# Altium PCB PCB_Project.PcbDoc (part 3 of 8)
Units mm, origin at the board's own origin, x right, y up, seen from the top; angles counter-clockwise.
Board outline 250 x 200 mm, 6 copper layers (Top Shielding/Sig, Sig 1, PWR, GND, Sig 4, Bottom Shielding/Sig), stack 1.568 mm thick; 736 components, 420 nets, 1929 pads, 2185 vias.
Unrouted connection lines stored in the file: 47.
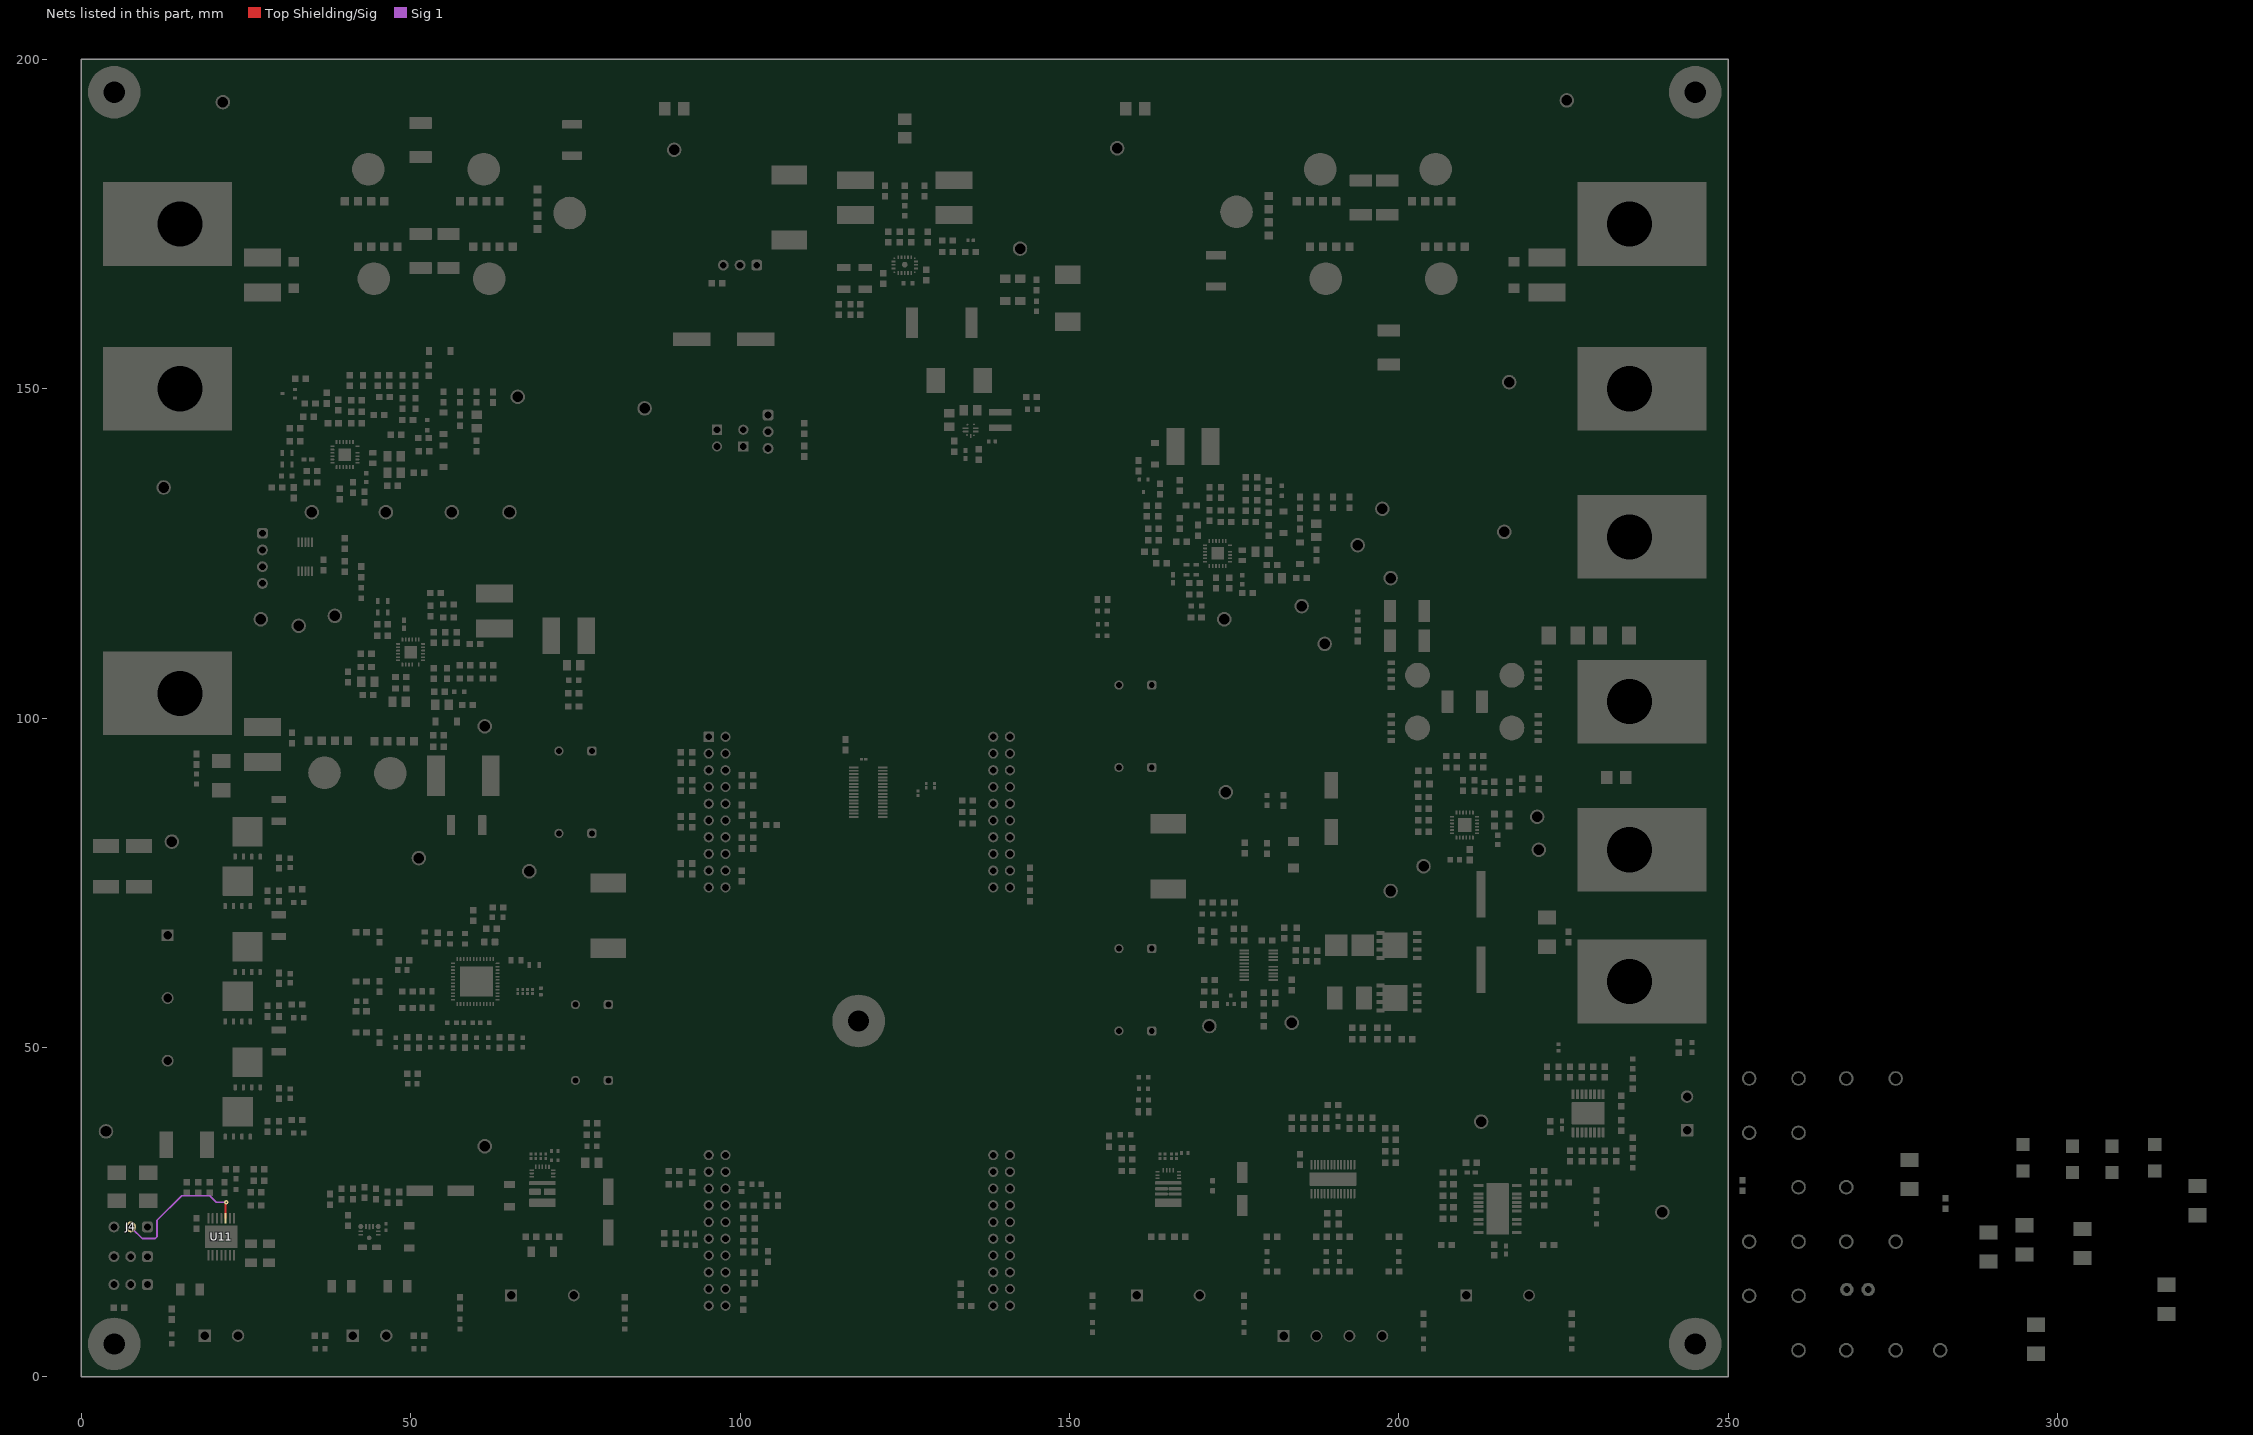
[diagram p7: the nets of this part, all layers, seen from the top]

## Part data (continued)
C44 C46 C64 C65 C118 C119 C124 C139 C146 C150 C154: library part CMP-0081011-1, "CAP, CERM, 0.1 µF, 100 V,+/- 10%, X7R, AEC-Q200 Grade 1, 0603", Cap_Case=0603, Manufacturer="Taiyo Yuden", Supplier Part Number 1=587-6009-1-ND, TempCo=X7R, Tolerance_%=10%, Value2=100V, ValueDisplayed=0.1µF
C45 C120 C123 C151 C153: library part CMP-0007082-4, "CAP, CERM, 0.01 uF, 100 V, +/- 10%, X7R, AEC-Q200 Grade 1, 0603", Cap_Case=0603, Manufacturer=TDK, Supplier Part Number 1=445-5812-1-ND, TempCo=X7R, Tolerance_%=10%, Value1="0.235428 ohm", Value2=100V, ValueDisplayed=0.01uF
C49: library part CMP-0007094-5, "CAP, CERM, 0.22 uF, 50 V, +/- 10%, X7R, AEC-Q200 Grade 1, 0603", Cap_Case=0603, Manufacturer=TDK, PartNumber=CGA3E3X7R1H224K080AB, Supplier Part Number 1=445-6926-1-ND, TempCo=X7R, Tolerance_%=10%, Value1="0.021699 ohm", Value2=50V, ValueDisplayed=0.22uF
C51 C125 C155: library part CMP-0007969-2, "CAP, CERM, 0.1 uF, 100 V, +/- 10%, X7R, AEC-Q200 Grade 1, 0805", Cap_Case=0805, Manufacturer=TDK, Supplier Part Number 1=445-5827-1-ND, TempCo=X7R, Tolerance_%=10%, Value1="0.020726 ohm", Value2=100V, ValueDisplayed=0.1uF
C52 C53 C58 C131 C133 C160 C162: library part CMP-0007079-4, "CAP, CERM, 0.047 uF, 50 V, +/- 10%, X7R, AEC-Q200 Grade 1, 0603", Cap_Case=0603, Manufacturer=TDK, Supplier Part Number 1=445-5664-1-ND, TempCo=X7R, Tolerance_%=10%, Value1="0.049007 ohm", Value2=50V, ValueDisplayed=0.047uF
C54 C127 C157: library part CMP-0006687-2, "CAP, CERM, 330 pF, 50 V, +/- 10%, X7R, 0402", Cap_Case=0402, Manufacturer=MuRata, Supplier Part Number 1=490-3247-1-ND, TempCo=X7R, Tolerance_%=10%, Value1=Unknown, Value2=50V, ValueDisplayed=330pF
C55: library part CMP-0007080-5, "CAP, CERM, 0.068 uF, 50 V, +/- 10%, X7R, AEC-Q200 Grade 1, 0603", Cap_Case=0603, Manufacturer=TDK, Supplier Part Number 1=445-5665-1-ND, TempCo=X7R, Tolerance_%=10%, Value1="0.035979 ohm", Value2=50V, ValueDisplayed=0.068uF
C56 C57 C130 C132 C159 C161: library part CMP-0006921-4, "CAP, CERM, 330 pF, 50 V, +/- 10%, X7R, 0603", Cap_Case=0603, Manufacturer=Kemet, Supplier Part Number 1=399-1073-1-ND, TempCo=X7R, Tolerance_%=10%, Value1=Unknown, Value2=50V, ValueDisplayed=330pF
C59 C129 C158: library part CMP-0095670-2, "Cap Ceramic 0.1uF 25V X7R 10% Pad SMD 0603 Soft Termination +125°C Automotive T/R", Manufacturer=Murata, Operating Temperature Range="-55°C to +125°C", TempCo=15%, Temperature Characteristic=X7R, Tolerance_%=10%, ValueDisplayed=0.1uF
C60 C61: library part CMP-0093675-1, "4.7uF ±10% 100V Ceramic Capacitor X7S 1210 (3225 Metric)", Manufacturer=Murata, Operating Temperature Range="-55°C to +125°C", TempCo=22%, Temperature Characteristic=X7S, Tolerance_%=10%, ValueDisplayed=4.7uF
C62 C63: library part CMP-0123888-1, "Ceramic Capacitor, 1206, 22uF, 20%, X7R, 15%, 16V", Manufacturer="Taiyo Yuden", Operating Temperature Range="-55°C to +125°C", TempCo=15%, Temperature Characteristic=X7R, Tolerance_%=20%, ValueDisplayed=22uF, Voltage=16V
C66: library part CMP-0081259-1, "CAP, CERM, 1 µF, 35 V,+/- 10%, X7R, AEC-Q200 Grade 1, 0603", Cap_Case=0603, Manufacturer=TDK, Supplier Part Number 1=445-174339-1-ND, TempCo=X7R, Tolerance_%=10%, Value2=35V, ValueDisplayed=1µF
C67: library part CMP-0011225-2, "CAP, AL, 47 uF, 100 V, +/- 20%, 0.32 ohm, AEC-Q200 Grade 2, SMD", Cap_Case=H13, Manufacturer=Panasonic, Supplier Part Number 1=PCE3497CT-ND, Tolerance_%=20%, Value1="0.32 ohm", Value2=100V, ValueDisplayed=47uF
C68: library part CMP-0122034-1, "10 pF ±10% 50V Ceramic Capacitor X7R 0402 (1005 Metric)", Digikey Part Number=399-C0402C100K5RAC7867CT-ND, Manufacturer=KEMET, Operating Temperature Range="-55°C to +125°C", TempCo=15%, Temperature Characteristic=X7R, Tolerance_%=10%, ValueDisplayed=10pF
C69: library part CMP-0008305-2, "CAP, CERM, 22 uF, 25 V, +/- 20%, X5R, 0805", Cap_Case=0805, Manufacturer=MuRata, Supplier Part Number 1=490-10749-1-ND, TempCo=X5R, Tolerance_%=20%, Value1=Unknown, Value2=25V, ValueDisplayed=22uF
C70: library part CMP-0008378-2, "CAP, CERM, 10 uF, 25 V, +/- 10%, X7R, 0805", Cap_Case=0805, Manufacturer=MuRata, Supplier Part Number 1=81-GRM21BZ71E106KE5L, TempCo=X7R, Tolerance_%=10%, Value1=Unknown, Value2=25V, ValueDisplayed=10uF
C71: library part CMP-0006696-2, "CAP, CERM, 6800 pF, 50 V, +/- 10%, X7R, 0402", Cap_Case=0402, Manufacturer=MuRata, Supplier Part Number 1=490-4515-1-ND, TempCo=X7R, Tolerance_%=10%, Value1=Unknown, Value2=50V, ValueDisplayed=6800pF
C72 C78 C81 C84 C86 C89 C90 C91: library part CMP-0007086-4, "CAP, CERM, 0.022 uF, 100 V, +/- 10%, X7R, AEC-Q200 Grade 1, 0603", Cap_Case=0603, Manufacturer=TDK, Supplier Part Number 1=445-5814-1-ND, TempCo=X7R, Tolerance_%=10%, Value1="0.083542 ohm", Value2=100V, ValueDisplayed=0.022uF
C73 C75 C82: library part CMP-0006356-2, "CAP, CERM, 0.1 uF, 50 V, +/- 10%, X7R, AEC-Q200 Grade 1, 0402", Cap_Case=0402, Manufacturer=MuRata, Supplier Part Number 1=490-10672-1-ND, TempCo=X7R, Tolerance_%=10%, Value1=Unknown, Value2=50V, ValueDisplayed=0.1uF
C77 C80: library part CMP-0007050-1, "CAP, CERM, 0.47 uF, 50 V, +/- 10%, X7R, 0603", Cap_Case=0603, Manufacturer=TDK, Supplier Part Number 1=445-5952-1-ND, TempCo=X7R, Tolerance_%=10%, Value1="0.010974 ohm", Value2=50V, ValueDisplayed=0.47uF
C87: library part CMP-0079579-1, "CAP, CERM, 0.22 µF, 50 V,+/- 10%, X7R, AEC-Q200 Grade 1, 0603", Cap_Case=0603, Manufacturer=MuRata, Supplier Part Number 1=490-14410-1-ND, TempCo=X7R, Tolerance_%=10%, Value2=50V, ValueDisplayed=0.22µF
C88 C92 C102 C140 C141 C142: library part CMP-0079095-1, "CAP, CERM, 0.1 µF, 50 V,+/- 10%, X7R, AEC-Q200 Grade 1, 0603", Cap_Case=0603, Manufacturer=AVX, Supplier Part Number 1=478-3540-1-ND, TempCo=X7R, Tolerance_%=10%, Value2=50V, ValueDisplayed=0.1µF
C93: library part CMP-0006850-4, "CAP, CERM, 0.01 uF, 50 V, +/- 5%, X7R, 0603", Cap_Case=0603, Manufacturer=Kemet, Supplier Part Number 1=399-1092-1-ND, TempCo=X7R, Tolerance_%=5%, Value1=Unknown, Value2=50V, ValueDisplayed=0.01uF
C94 C99 C100: library part CMP-0084736-1, "CAP, CERM, 0.1 µF, 50 V,+/- 10%, X7R, AEC-Q200 Grade 0, 0603", Cap_Case=0603, Manufacturer=AVX, TempCo=X7R, Tolerance_%=10%, Value2=50V, ValueDisplayed=0.1µF
C95: library part CMP-0077295-1, "CAP, AL, 100 µF, 50 V, +/- 20%, 0.18 ohm, AEC-Q200 Grade 2, SMD", Cap_Case=8x10.2mm, Manufacturer=Panasonic, Supplier Part Number 1=P19726CT-ND, Tolerance_%=20%, Value1="0.18 ohm", Value2=50V, ValueDisplayed=100µF
C96: library part CMP-0007353-5, "CAP, CERM, 2.2 uF, 50 V, +/- 10%, X5R, 0603", Cap_Case=0603, Manufacturer=MuRata, Supplier Part Number 1=490-10733-1-ND, TempCo=X5R, Tolerance_%=10%, Value1=Unknown, Value2=50V, ValueDisplayed=2.2uF
C97: library part CMP-0093561-1, "Cap Ceramic 5.6nF 50V X7R ±10% Pad SMD 0603 +125°C T/R", Manufacturer=Samsung, Operating Temperature Range="-55°C to +125°C", TempCo=0.15, Temperature Characteristic=X7R, Tolerance_%=10%, ValueDisplayed=5.6nF
C98: library part CMP-0007094-5, "CAP, CERM, 0.22 uF, 50 V, +/- 10%, X7R, AEC-Q200 Grade 1, 0603", Cap_Case=0603, Manufacturer=TDK, Supplier Part Number 1=445-6926-1-ND, TempCo=X7R, Tolerance_%=10%, Value1="0.021699 ohm", Value2=50V, ValueDisplayed=0.22uF
C101: library part CMP-0006922-4, "CAP, CERM, 3300 pF, 50 V, +/- 10%, X7R, 0603", Cap_Case=0603, Manufacturer=Kemet, Supplier Part Number 1=399-1086-1-ND, TempCo=X7R, Tolerance_%=10%, Value1=Unknown, Value2=50V, ValueDisplayed=3300pF
C103 C104 C111: library part CMP-0008495-2, "CAP, CERM, 0.022 uF, 100 V, +/- 5%, X7R, 1206", Cap_Case=1206, Manufacturer=AVX, Supplier Part Number 1=478-3789-1-ND, TempCo=X7R, Tolerance_%=5%, Value1="0.079 ohm", Value2=100V, ValueDisplayed=0.022uF
C107: library part CMP-0008709-1, "CAP, CERM, 0.1 uF, 100 V, +/- 10%, X7R, 1206", Cap_Case=1206_180, Manufacturer=TDK, Supplier Part Number 1=445-1377-1-ND, TempCo=X7R, Tolerance_%=10%, Value1="0.030343 ohm", Value2=100V, ValueDisplayed=0.1uF
C108 C166 C170 C176 C178 C183 C185: library part CMP-0079247-1, "CAP, CERM, 4700 pF, 100 V,+/- 10%, X7R, AEC-Q200 Grade 1, 0603", Cap_Case=0603, Manufacturer=MuRata, Supplier Part Number 1=490-4930-1-ND, TempCo=X7R, Tolerance_%=10%, Value2=100V, ValueDisplayed=4700pF
C109: library part CMP-0008881-2, "CAP, CERM, 0.1 uF, 100 V, +/- 10%, X7R, 1206", Cap_Case=1206, Manufacturer=MuRata, Supplier Part Number 1=490-3364-1-ND, TempCo=X7R, Tolerance_%=10%, Value1=Unknown, Value2=100V, ValueDisplayed=0.1uF
C110: library part CMP-0008713-2, "CAP, CERM, 0.22 uF, 100 V, +/- 10%, X7R, 1206", Cap_Case=1206, Manufacturer=TDK, Supplier Part Number 1=445-2283-1-ND, TempCo=X7R, Tolerance_%=10%, Value1="0.01493 ohm", Value2=100V, ValueDisplayed=0.22uF
C112 C128 C199: library part CMP-0007135-2, "CAP, CERM, 0.1 uF, 16 V, +/- 10%, X7R, AEC-Q200 Grade 1, 0603", Cap_Case=0603, Manufacturer=MuRata, Supplier Part Number 1=490-8015-1-ND, TempCo=X7R, Tolerance_%=10%, Value1=Unknown, Value2=16V, ValueDisplayed=0.1uF
C114 C116 C122 C144 C147 C152: library part CMP-0077895-3, "CAP, CERM, 0.22 µF, 100 V,+/- 20%, X7S, AEC-Q200 Grade 1, 0603", Cap_Case=0603, Manufacturer="Taiyo Yuden", Supplier Part Number 1=587-5013-1-ND, TempCo=X7S, Tolerance_%=20%, Value2=100V, ValueDisplayed=0.22µF
C134: library part CMP-0007430-2, "CAP, CERM, 0.082 uF, 25 V, +/- 10%, X7R, 0603", Cap_Case=0603, Manufacturer=MuRata, Supplier Part Number 1=GRM188R71E823KA01D-ND, TempCo=X7R, Tolerance_%=10%, Value1=Unknown, Value2=25V, ValueDisplayed=0.082uF
C135: library part CMP-0011162-2, "CAP, AL, 220 uF, 63 V, +/- 20%, 0.16 ohm, SMD", Cap_Case=12.5x13.5, Manufacturer="Cornell Dubilier Electronics", Supplier Part Number 1=338-2175-1-ND, Tolerance_%=20%, Value1="0.16 ohm", Value2=63V, ValueDisplayed=220uF
C136: library part CMP-0007078-1, "CAP, CERM, 0.1 uF, 50 V, +/- 10%, X7R, AEC-Q200 Grade 1, 0603", Cap_Case=0603, Manufacturer=TDK, Supplier Part Number 1=445-5666-1-ND, TempCo=X7R, Tolerance_%=10%, Value1="0.0296 ohm", Value2=50V, ValueDisplayed=0.1uF
C137 C138: library part CMP-0006901-3, "CAP, CERM, 0.022 uF, 50 V, +/- 10%, X7R, 0603", Cap_Case=0603, Manufacturer=Kemet, Supplier Part Number 1=399-1280-1-ND, TempCo=X7R, Tolerance_%=10%, Value1=Unknown, Value2=50V, ValueDisplayed=0.022uF
C163: library part CMP-0123897-1, "Auto Grade Capacitor, 0603, X7R, 25V, 1uF, ±10%", Digikey Part Number=2679-AGC0603X7R250-105KXPTR-ND, Manufacturer=Venkel, Operating Temperature Range="-55°C to +125°C", TempCo=15%, Temperature Characteristic=X7R, Tolerance_%=10%, ValueDisplayed=1uF
C164: library part CMP-0007007-3, "CAP, CERM, 10 uF, 25 V, +/- 20%, X5R, 0603", Cap_Case=0603, Manufacturer=TDK, Supplier Part Number 1=445-9015-1-ND, TempCo=X5R, Tolerance_%=20%, Value1="0.004639 ohm", Value2=25V, ValueDisplayed=10uF
C165 C169 C175 C177 C182 C184: library part CMP-0007148-4, "CAP, CERM, 3300 pF, 100 V, +/- 10%, X7R, AEC-Q200 Grade 1, 0603", Cap_Case=0603, Manufacturer=MuRata, Supplier Part Number 1=GCM188R72A332KA37D-ND, TempCo=X7R, Tolerance_%=10%, Value1=Unknown, Value2=100V, ValueDisplayed=3300pF
C167: library part CMP-0007007-3, "CAP, CERM, 10 uF, 25 V, +/- 20%, X5R, 0603", Cap_Case=0603, Manufacturer=TDK, PartNumber=C1608X5R1E106M080AC, Supplier Part Number 1=445-9015-1-ND, TempCo=X5R, Tolerance_%=20%, Value1="0.004639 ohm", Value2=25V, ValueDisplayed=10uF
C168 C174 C180: library part CMP-0085951-1, "CAP, CERM, 10 µF, 75 V,+/- 20%, X7R, AEC-Q200 Grade 1, 1210", Cap_Case=1210, Manufacturer=TDK, TempCo=X7R, Tolerance_%=20%, Value2=75V, ValueDisplayed=10µF
C171 C172: library part CMP-0125363-1, "1 µF ±10% 100V Ceramic Capacitor X7T 0603 (1608 Metric)", Digikey Part Number=490-GRM188D72A105KE01DCT-ND, Manufacturer=Murata, Mouser Part Number=81-GRM188D72A105KE1D, Operating Temperature Range="-55°C to +125°C", TempCo=+22/-33%, Temperature Characteristic=X7T, Tolerance_%=10%, ValueDisplayed=1uF
C173 C179 C181: library part CMP-0121052-1, "Cap Ceramic 1uF 25V X7R ±10% Pad SMD 0603 +125°C T/R", Digikey Part Number=1276-CL10B105KA8VPJCCT-ND, Manufacturer=Samsung, Mouser Part Number=187-CL10B105KA8VPJC, Operating Temperature Range="-55°C to +125°C", TempCo=15%, Temperature Characteristic=X7R, Tolerance_%=10%, ValueDisplayed=1uF
C186 C187 C188: library part CMP-0006940-4, "CAP, CERM, 470 pF, 50 V, +/- 10%, X7R, 0603", Cap_Case=0603, Manufacturer=Kemet, Supplier Part Number 1=399-1075-1-ND, TempCo=X7R, Tolerance_%=10%, Value1=Unknown, Value2=50V, ValueDisplayed=470pF
C189: library part CMP-0121051-1, "Automotive CAP, 100㎋, 25V, ±10%, X7R, 0603, 5mm Bending", Manufacturer=Samsung, Mouser Part Number=187-CL10B104KA8VPJC, Operating Temperature Range="-55°C to +125°C", TempCo=15%, Temperature Characteristic=X7R, Tolerance_%=10%, ValueDisplayed=100nF
D1 D2 D4 D5 D7 D11 D13 D15 D16 D17 D18 D20 D21 D22 D23 D27 D29 D30 D31 D35 D40 D47 D48 D49: library part CMP-0078478-1, "LED, Green, SMD", Color=Green, Manufacturer=Lite-On, Power_TotalModule=75mW, Supplier Part Number 1=160-1446-1-ND, Value1=0.075W, Value2=2V
D3 D9 D14 D19 D28 D37 D41 D42 D46 D50: library part CMP-0002893-1, "LED, Super Red, SMD", Color="super red", Manufacturer="Wurth Elektronik", Supplier Part Number 1=732-4979-1-ND, Value1=W, Value2=1.9V
D6 D38 D59 D60 D61 D62 D63 D64 D65: library part CMP-0028987-2, "Diode, Schottky, 100 V, 2 A, SMB", Manufacturer=Vishay-Semiconductor, Value1=2A, Value2=0.79V
D8 D36 D45 D51 D52 D53 D54: library part CMP-0076974-1, "Diode, Switching, 100 V, 0.15 A, SOD-123", Manufacturer="Micro Commercial Components", Supplier Part Number 1=1N4148WTPMSCT-ND, Value1=0.15A, Value2=1.25V
D10: library part CMP-0077028-2, "Diode, Ultrafast, 400 V, 3 A, SMC", Manufacturer=Vishay-Semiconductor, Value1=3A, Value2=1.1V
D12: library part CMP-0067546-2, "Diode, Superfast Rectifier, 600 V, 5 A, SMC", Manufacturer="SMC Diode Solutions", Value1=5A, Value2=1.7V
D24 D32 D33 D43: library part CMP-0029014-2, "Diode, Ultrafast, 400 V, 1 A, 1408 Diode", Manufacturer=Bourns, Value1=1A, Value2=1.05V
D25 D26: library part CMP-0005541-4, "Diode, TVS, Uni, 13 V, 21.5 Vc, SMB", Manufacturer="Diodes Inc.", Value1=600W
D34 D44: library part CMP-0085022-1, "Diode, TVS, Bi, 51 V, 82.4 Vc, 400 W, 4.9 A, SMA (non-polarized)", Manufacturer=Littelfuse, Value1=82.4V
D39: library part CMP-0085010-1, "Diode, TVS, Bi, 20 V, 32.4 Vc, 400 W, 12.3 A, SMA (non-polarized)", Manufacturer=Littelfuse, Value1=32.4V
D55 D56 D57 D58: library part CMP-0028752-1, "Diode, Schottky, 150 V, 1 A, SMA", Manufacturer=STMicroelectronics, Supplier Part Number 1=497-7545-1-ND, Value1=1A, Value2=0.78V
H1 H2 H3 H4 H5: library part CMP-0003617-1, "Machine Screw, Round, #4-40 x 1/4, Nylon, Philips panhead", Manufacturer="B&F Fastener Supply", Supplier Part Number 1=H542-ND
H6 H7 H8 H9 H10: library part CMP-0003610-1, "Standoff, Hex, 0.5\"L #4-40 Nylon", Manufacturer=Keystone, Supplier Part Number 1=36-1902C-ND
J1 J2 J3 J4 J19: library part CMP-0075407-2, "Header, 100mil, 3x1, Gold, TH", Color=Black, Current_A=6.3A, Manufacturer=Samtec, PartNumber=TSW-103-07-G-S, Supplier Part Number 1=SAM1029-03-ND, Voltage_V=550V
J5: library part CMP-0055528-1, "Terminal Block, 9.52mm, 3x1, R/A, TH", Color=Green, Current_A=32A, Manufacturer="Phoenix Contact", PartNumber=1904150, Supplier Part Number 1=277-6184-ND, Voltage_V=1kV
J6 J7 J11: library part CMP-0055471-1, "Terminal Block, 5.08 mm, 2x1, TH", Color=Green, Current_A=17.5A, Manufacturer="Phoenix Contact", PartNumber=1715721, Supplier Part Number 1=277-1263-ND, Voltage_V=400V
J8 J9 J10: library part CMP-0055527-1, "Terminal Block, 9.52mm, 2x1, R/A, TH", Color=Green, Current_A=32A, Manufacturer="Phoenix Contact", PartNumber=1902547, Supplier Part Number 1=277-5951-ND, Voltage_V=1kV
J12: library part CMP-0055526-1, "Terminal Block, 5mm, 4x1, R/A,TH", Color=Green, Current_A=17.5A, Manufacturer="Phoenix Contact", PartNumber=1715048, Supplier Part Number 1=277-1260-ND, Voltage_V=400V
J13: library part CMP-0003837-2, "Receptacle, 2.54mm, 10x2, Tin, TH", Alternate Manufacturer="Major League Electronics", Alternate PartNumber=CRD-081413-A-G, Manufacturer=Samtec, Supplier Part Number 1=SAM1204-10-ND
J14: library part CMP-0078266-2, "Receptacle, 2.54mm, 10x2, Tin, TH", Alternate Manufacturer="Major League Electronics", Alternate PartNumber=CRD-081413-A-G, Manufacturer=Samtec, Supplier Part Number 1=SAM1204-10-ND
J15: library part CMP-0081071-3, "Receptacle, 2.54mm, 10x2, Tin, TH", Alternate Manufacturer="Major League Electronics", Alternate PartNumber=CRD-081413-A-G, Manufacturer=Samtec, Supplier Part Number 1=SAM1204-10-ND
J16 J17: library part CMP-0075286-1, "Header, 2.54mm, 2x1, Gold, TH", Color=Black, Current_A=3A, Manufacturer=Foxconn, PartNumber=HB3902U, Voltage_V=500V
J18: library part CMP-0081070-3, "Receptacle, 2.54mm, 10x2, Tin, TH", Alternate Manufacturer="Major League Electronics", Alternate PartNumber=CRD-081413-A-G, Manufacturer=Samtec, Supplier Part Number 1=SAM1204-10-ND
J20: library part CMP-0075409-2, "Header, 100mil, 4x1, Gold, TH", Color=Black, Current_A=6.3A, Manufacturer=Samtec, PartNumber=TSW-104-07-G-S, Supplier Part Number 1=SAM1029-04-ND, Voltage_V=550V
L1 L2: library part CMP-0063986-1, "Inductor, Shielded Drum Core, Ferrite, 1 uH, 24 A, 0.0012 ohm, SMD", Manufacturer="Wurth Elektronik", Supplier Part Number 1=732-2138-1-ND, Value1="0.0012 ohm", Value2=24A, ValueDisplayed=1uH
L3: library part CMP-0063847-1, "Inductor, Shielded Drum Core, Ferrite, 2.2 uH, 5.9 A, 0.0104 ohm, SMD", Manufacturer="Wurth Elektronik", Supplier Part Number 1=732-1055-1-ND, Value1="0.0104 ohm", Value2=5.9A, ValueDisplayed=2.2uH
L4: library part CMP-0064538-2, "Inductor, Shielded Drum Core, Ferrite, 22 uH, 5.3 A, 0.0233 ohm, SMD", Manufacturer="Wurth Elektronik", Supplier Part Number 1=732-1243-1-ND, Value1="0.0233 ohm", Value2=5.3A, ValueDisplayed=22uH
L5: library part CMP-0090842-1, "Power Inductor, shielded, composite, 1uH 20% tol, DCR 7.2mOhms, SRF 65MHz, Isat 4.8A, Irms 13A, AEC-Q200", Manufacturer=Coilcraft, Operating Temperature Range="to +165°C", Self Resonant Frequency=65MHz, Test Frequency=1MHz, Tolerance_%=20%
LBL1: library part CMP-0003625-1, "Thermal Transfer Printable Labels, 0.650\" W x 0.200\" H - 10,000 per roll", Manufacturer=Brady, Supplier Part Number 1=97C5133
LOGO1: library part CMP-0074837-1, "IEC 61010-1 Hot Surface Warning"
Logo2: library part CMP-0074844-1
Logo3: library part CMP-0074838-1, "Texas Instrument Corporate Signature"
Logo4: library part CMP-0074847-1, "FCC_disclaimer"
Logo5: library part CMP-0074769-1
Q1 Q2 Q7 Q9 Q10 Q11 Q12 Q17 Q18 Q19 Q20 Q21: library part CMP-0088066-1, "N-Channel Power MOSFET 80V 3374A 1.1mOhm 8-Pin DFNW Surface Mount T/R", Manufacturer="ON Semiconductor"
Q3 Q4 Q5 Q6: library part CMP-0098150-1, "Trans MOSFET N-CH 40V 190A Automotive 5-Pin(4+Tab) LFPAK T/R", Digikey Part Number=1727-7419-1-ND, Drain To Source Breakdown Voltage=42V, Input Capacitace At Vds="5436pF @ 25V", Manufacturer=Nexperia, Mouser Part Number=771-BUK7J1R4-40HX, Operating Temperature Range="-55°C to +175°C", Power_W=395W, Pulse Drain Current=600A, Typ Forward Diode Voltage=0.8V
Q13 Q22: library part CMP-0000757-1, "MOSFET, N-CH, 50 V, 0.2 A, SOT-323", Alternate Manufacturer=None, Manufacturer="Diodes Inc.", Supplier Part Number 1=BSS138W-FDICT-ND, Value1=3
Q14 Q15: library part CMP-0000870-1, "MOSFET, N-CH, 60 V, 60 A, PowerPAK SO-8", Alternate Manufacturer=None, Manufacturer=Vishay-Semiconductor, Supplier Part Number 1=SIR662DP-T1-GE3CT-ND, Value1=0.002, Value2="96 nC"
Q16: library part CMP-0000428-2, "Transistor, NPN, 40 V, 0.2 A, SOT-416", Manufacturer="ON Semiconductor", Supplier Part Number 1=MMBT3904TT1GOSCT-ND, Value1="0.2 A", Value2=300
Q23 Q24 Q25 Q26 Q27 Q28: library part CMP-0000962-2, "MOSFET, N-CH, 100 V, 10 A, DQJ0008A (VSONP-8)", Alternate Manufacturer=None, Manufacturer="Texas Instruments", Value2="17 nC"
R1 R2 R69 R70 R77 R78 R105 R106 R107 R108 R116 R199: library part CMP-0023266-5, "RES, 750, 1%, 0.1 W, 0603", Manufacturer=Yageo, Power_W=100mW, Supplier Part Number 1=311-750HRCT-ND, TempCo="100 ppm/C", Tolerance_%=1%, Value2=0.1W, Value_Code=750R, ValueDisplayed=750
R3 R39 R64 R104 R136 R183 R214 R215 R244 R267: library part CMP-0022904-5, "RES, 205, 1%, 0.1 W, 0603", Manufacturer=Yageo, Power_W=100mW, Supplier Part Number 1=311-205HRCT-ND, TempCo="100 ppm/C", Tolerance_%=1%, Value2=0.1W, Value_Code=205R, ValueDisplayed=205
R4: library part CMP-0025886-3, "RES, 10 k, 5%, 0.1 W, 0603", Manufacturer="Yageo America", Power_W=100mW, Supplier Part Number 1=311-10KGRCT-ND, TempCo="100 ppm/C", Tolerance_%=5%, Value2=0.1W, Value_Code=10k0, ValueDisplayed=10k
R5 R12: library part CMP-0025697-4, "RES, 0, 5%, 0.1 W, AEC-Q200 Grade 0, 0603", Manufacturer=Vishay-Dale, PartNumber=CRCW06030000Z0EA, Power_W=100mW, Supplier Part Number 1=541-0.0GCT-ND, TempCo="200 ppm/C", Tolerance_%=5%, Value2=0.1W, Value_Code=0000, ValueDisplayed=0
R6 R18 R61 R88 R257: library part CMP-0094798-1, "Res Thick Film 0402 10K Ohm 5% 0.063W(1/16W) ±100ppm/C Pad SMD T/R", Digikey Part Number=311-10KJRCT-ND, Manufacturer=YAGEO, Mouser Part Number=603-RC0402JR-0710KL, Operating Temperature Range="-55°C to +155°C", Power_W=63mW, TempCo=100ppm/°C, Tolerance_%=5%
R7 R9 R10 R11 R13 R17 R19 R20 R256 R258 R259 R260 R293 R294 R295 R296: library part CMP-0027500-1, "RES, 22.0, 1%, 0.05 W, 0201", Manufacturer="Yageo America", Power_W=50mW, Supplier Part Number 1=YAG2518CT-ND, TempCo="200 ppm/C", Tolerance_%=1%, Value2=0.05W, Value_Code=22R0, ValueDisplayed=22.0
R8: library part CMP-0022109-5, "RES, 1.00 k, 1%, 0.1 W, AEC-Q200 Grade 0, 0603", Manufacturer=Vishay-Dale, Power_W=100mW, Supplier Part Number 1=541-1.00KHCT-ND, TempCo="100 ppm/C", Tolerance_%=1%, Value2=0.1W, Value_Code=1k00, ValueDisplayed=1.00k
R14 R176 R178 R181 R185 R187 R237 R239 R242 R246 R248 R302: library part CMP-0022895-5, "RES, 1.00 k, 1%, 0.1 W, 0603", Manufacturer=Yageo, Power_W=100mW, Supplier Part Number 1=311-1.00KHRCT-ND, TempCo="100 ppm/C", Tolerance_%=1%, Value2=0.1W, Value_Code=1k00, ValueDisplayed=1.00k
R15 R16 R30 R139 R140 R150 R161 R253 R254 R255: library part CMP-0022990-5, "RES, 2.49 k, 1%, 0.1 W, 0603", Manufacturer=Yageo, Power_W=100mW, Supplier Part Number 1=311-2.49KHRCT-ND, TempCo="100 ppm/C", Tolerance_%=1%, Value2=0.1W, Value_Code=2k49, ValueDisplayed=2.49k
R21 R153 R216: library part CMP-0098465-1, "1 Ohms ±1% 3W Chip Resistor 2010 (5025 Metric) Automotive AEC-Q200, Current Sense, Moisture Resistant, Pulse Withstanding", Digikey Part Number=4423-VMP-1R00-1.0-UCT-ND, Manufacturer=Isabellenhuette, Operating Temperature Range="-65°C to +170°C", Power_W=3W, TempCo=20ppm/°C, Tolerance_%=1%
R22 R23 R24 R28 R29 R32 R38 R117 R154 R155 R157 R163 R164 R165 R179 R182 R196 R197 R204 R206 R209 R217 R218 R219 R224 R225 R226 R240 R243 R305: library part CMP-0025697-4, "RES, 0, 5%, 0.1 W, AEC-Q200 Grade 0, 0603", Manufacturer=Vishay-Dale, Power_W=100mW, Supplier Part Number 1=541-0.0GCT-ND, TempCo="200 ppm/C", Tolerance_%=5%, Value2=0.1W, Value_Code=0000, ValueDisplayed=0
R25 R158 R174 R221 R234: library part CMP-0021863-2, "RES, 10.0, 1%, 0.125 W, 0805", Manufacturer="Yageo America", Power_W=125mW, Supplier Part Number 1=311-10.0CRCT-ND, TempCo="200 ppm/C", Tolerance_%=1%, Value2=0.125W, Value_Code=10R0, ValueDisplayed=10.0
R26: library part CMP-0092921-1, "Res Metal Strip 3921 0.0005 Ohm 1% 3W ±175ppm/°C Molded SMD SMD Embossed Plastic T/R", Digikey Part Number=WSLM-.0005CT-ND, Manufacturer="Vishay Dale", Mouser Part Number=71-WSL3921L5000FEA, Operating Temperature Range="-65°C to +170°C", Power_W=3W, TempCo=150ppm/°C, Tolerance_%=1%
R27 R166 R227: library part CMP-0022679-3, "RES, 100, 1%, 0.1 W, AEC-Q200 Grade 0, 0603", Manufacturer=Panasonic, Power_W=100mW, Supplier Part Number 1=P100HCT-ND, TempCo="100 ppm/C", Tolerance_%=1%, Value2=0.1W, Value_Code=100R, ValueDisplayed=100
R31 R58 R167 R168 R228 R229: library part CMP-0022902-5, "RES, 200, 1%, 0.1 W, 0603", Manufacturer=Yageo, Power_W=100mW, Supplier Part Number 1=311-200HRCT-ND, TempCo="100 ppm/C", Tolerance_%=1%, Value2=0.1W, Value_Code=200R, ValueDisplayed=200
R33 R169 R170 R171 R173 R193 R202 R230 R231 R232 R233: library part CMP-0023007-4, "RES, 2.21, 1%, 0.1 W, 0603", Manufacturer=Yageo, Power_W=100mW, Supplier Part Number 1=311-2.21HRCT-ND, TempCo="200 ppm/C", Tolerance_%=1%, Value2=0.1W, Value_Code=2R21, ValueDisplayed=2.21
R34: library part CMP-0021863-2, "RES, 10.0, 1%, 0.125 W, 0805", Manufacturer="Yageo America", PartNumber=RC0805FR-0710RL, Power_W=125mW, Supplier Part Number 1=311-10.0CRCT-ND, TempCo="200 ppm/C", Tolerance_%=1%, Value2=0.125W, Value_Code=10R0, ValueDisplayed=10.0
R35 R129 R130 R134 R138 R141 R142 R149 R152 R304: library part CMP-0023626-3, "RES, 10.0 k, 0.01%, 0.063 W, 0603", Manufacturer="Stackpole Electronics Inc", Power_W=63mW, Supplier Part Number 1=RNCF0603TKY10K0CT-ND, TempCo="5 ppm/C", Tolerance_%=0.01%, Value2=0.063W, Value_Code=10k0, ValueDisplayed=10.0k
R36: library part CMP-0023288-5, "RES, 820, 1%, 0.1 W, 0603", Manufacturer=Yageo, Power_W=100mW, Supplier Part Number 1=311-820HRCT-ND, TempCo="100 ppm/C", Tolerance_%=1%, Value2=0.1W, Value_Code=820R, ValueDisplayed=820
R37 R180 R241: library part CMP-0023017-5, "RES, 309, 1%, 0.1 W, 0603", Manufacturer=Yageo, Power_W=100mW, Supplier Part Number 1=311-309HRCT-ND, TempCo="100 ppm/C", Tolerance_%=1%, Value2=0.1W, Value_Code=309R, ValueDisplayed=309
R40 R41 R184 R186 R245 R247 R262: library part CMP-0025686-1, "RES, 10.0 k, 0.1%, 0.1 W, AEC-Q200 Grade 1, 0603", Manufacturer=Vishay-Dale, Power_W=100mW, Supplier Part Number 1=TNP10.0KAACT-ND, TempCo="25 ppm/C", Tolerance_%=0.1%, Value2=0.1W, Value_Code=10k0, ValueDisplayed=10.0k
R42: library part CMP-0022449-4, "RES, 4.02 k, 1%, 0.1 W, AEC-Q200 Grade 0, 0603", Manufacturer=Vishay-Dale, Power_W=100mW, Supplier Part Number 1=541-4.02KHCT-ND, TempCo="100 ppm/C", Tolerance_%=1%, Value2=0.1W, Value_Code=4k02, ValueDisplayed=4.02k
R43: library part CMP-0022779-5, "RES, 12.0 k, 1%, 0.1 W, 0603", Manufacturer=Yageo, Power_W=100mW, Supplier Part Number 1=311-12.0KHRCT-ND, TempCo="100 ppm/C", Tolerance_%=1%, Value2=0.1W, Value_Code=12k0, ValueDisplayed=12.0k
R44 R190 R251 R261 R265 R266 R270 R273 R277: library part CMP-0021990-4, "RES, 100 k, 1%, 0.1 W, AEC-Q200 Grade 0, 0603", Manufacturer=Vishay-Dale, Power_W=100mW, Supplier Part Number 1=541-100KHCT-ND, TempCo="100 ppm/C", Tolerance_%=1%, Value2=0.1W, Value_Code=100k
R45 R127 R252: library part CMP-0023098-5, "RES, 40.2 k, 1%, 0.1 W, 0603", Manufacturer=Yageo, Power_W=100mW, Supplier Part Number 1=311-40.2KHRCT-ND, TempCo="100 ppm/C", Tolerance_%=1%, Value2=0.1W, Value_Code=40k2, ValueDisplayed=40.2k
R46: library part CMP-0022188-4, "RES, 1.54, 1%, 0.1 W, AEC-Q200 Grade 0, 0603", Manufacturer=Vishay-Dale, Power_W=100mW, Supplier Part Number 1=541-1.54HHCT-ND, TempCo="100 ppm/C", Tolerance_%=1%, Value2=0.1W, Value_Code=1R54, ValueDisplayed=1.54
R47: library part CMP-0023163-5, "RES, 510, 1%, 0.1 W, 0603", Manufacturer=Yageo, Power_W=100mW, Supplier Part Number 1=311-510HRCT-ND, TempCo="100 ppm/C", Tolerance_%=1%, Value2=0.1W, Value_Code=510R, ValueDisplayed=510
R48 R56 R57 R62 R123 R124 R125 R208 R210: library part CMP-0022684-3, "RES, 10.0 k, 1%, 0.1 W, 0603", Manufacturer=Panasonic, Power_W=100mW, Supplier Part Number 1=P10.0KHCT-ND, TempCo="100 ppm/C", Tolerance_%=1%, Value2=0.1W, Value_Code=10k0, ValueDisplayed=10.0k
R49 R50: library part CMP-0023630-1, "RES, 100 k, 0.1%, 0.1 W, 0603", Manufacturer="Yageo America", Power_W=100mW, Supplier Part Number 1=603-RT0603BRD07100KL, TempCo="25 ppm/C", Tolerance_%=0.1%, Value2=0.1W, Value_Code=100k
R51: library part CMP-0022684-3, "RES, 10.0 k, 1%, 0.1 W, 0603", Manufacturer=Panasonic, Power_W=100mW, Supplier Part Number 1=P10.0KHCT-ND, TempCo="100 ppm/C", Tolerance_%=1%, Value2=0.1W, Value_Code=10k0, ValueDisplayed=150k
R52 R53: library part CMP-0023330-5, "RES, 97.6 k, 1%, 0.1 W, 0603", Manufacturer=Yageo, Power_W=100mW, Supplier Part Number 1=311-97.6KHRCT-ND, TempCo="100 ppm/C", Tolerance_%=1%, Value2=0.1W, Value_Code=97k6, ValueDisplayed=97.6k
R54 R55: library part CMP-0023335-5, "RES, 9.53 k, 1%, 0.1 W, 0603", Manufacturer=Yageo, Power_W=100mW, Supplier Part Number 1=311-9.53KHRCT-ND, TempCo="100 ppm/C", Tolerance_%=1%, Value2=0.1W, Value_Code=9k53, ValueDisplayed=9.53k
R59: library part CMP-0022014-4, "RES, 118 k, 1%, 0.1 W, AEC-Q200 Grade 0, 0603", Manufacturer=Vishay-Dale, Power_W=100mW, Supplier Part Number 1=541-118KHCT-ND, TempCo="100 ppm/C", Tolerance_%=1%, Value2=0.1W, Value_Code=118k
R60 R137: library part CMP-0022957-5, "RES, 26.1 k, 1%, 0.1 W, 0603", Manufacturer=Yageo, Power_W=100mW, Supplier Part Number 1=311-26.1KHRCT-ND, TempCo="100 ppm/C", Tolerance_%=1%, Value2=0.1W, Value_Code=26k1, ValueDisplayed=26.1k
R63 R76 R191 R205 R281 R282 R283 R287 R288 R289 R300 R306 R307: library part CMP-0022751-4, "RES, 10.0, 1%, 0.1 W, 0603", Manufacturer=Yageo, Power_W=100mW, Supplier Part Number 1=311-10.0HRCT-ND, TempCo="100 ppm/C", Tolerance_%=1%, Value2=0.1W, Value_Code=10R0, ValueDisplayed=10.0
R65 R67 R68 R72 R83 R86 R87 R89: library part CMP-0025700-3, "RES, 100, 5%, 0.1 W, 0603", Manufacturer=Vishay-Dale, Power_W=100mW, Supplier Part Number 1=541-100GCT-ND, TempCo="200 ppm/C", Tolerance_%=5%, Value2=0.1W, Value_Code=100R, ValueDisplayed=100
R66 R71 R74 R75 R79 R80 R81 R84 R90 R91 R92 R93 R94 R95 R96 R99 R100 R101: library part CMP-0023341-2, "RES, 10.0 k, 1%, 0.1 W, AEC-Q200 Grade 0, 0603", Manufacturer="Stackpole Electronics Inc", Power_W=100mW, Supplier Part Number 1=RMCF0603FT10K0CT-ND, TempCo="100 ppm/C", Tolerance_%=1%, Value2=0.1W, Value_Code=10k0, ValueDisplayed=10.0k
R73 R85 R177 R238: library part CMP-0023243-5, "RES, 698, 1%, 0.1 W, 0603", Manufacturer=Yageo, Power_W=100mW, Supplier Part Number 1=311-698HRCT-ND, TempCo="100 ppm/C", Tolerance_%=1%, Value2=0.1W, Value_Code=698R, ValueDisplayed=698
R82 R131 R132: library part CMP-0023153-5, "RES, 4.70 k, 1%, 0.1 W, 0603", Manufacturer=Yageo, Power_W=100mW, Supplier Part Number 1=311-4.70KHRCT-ND, TempCo="100 ppm/C", Tolerance_%=1%, Value2=0.1W, Value_Code=4k70, ValueDisplayed=4.70k
R97 R98: library part CMP-0022458-4, "RES, 4.99 k, 1%, 0.1 W, AEC-Q200 Grade 0, 0603", Manufacturer=Vishay-Dale, Power_W=100mW, Supplier Part Number 1=541-4.99KHCT-ND, TempCo="100 ppm/C", Tolerance_%=1%, Value2=0.1W, Value_Code=4k99, ValueDisplayed=4.99k
R102: library part CMP-0022228-4, "RES, 23.2 k, 1%, 0.1 W, AEC-Q200 Grade 0, 0603", Manufacturer=Vishay-Dale, Power_W=100mW, Supplier Part Number 1=541-23.2KHCT-ND, TempCo="100 ppm/C", Tolerance_%=1%, Value2=0.1W, Value_Code=23k2, ValueDisplayed=23.2k
R103: library part CMP-0084244-1, "RES, 1.0 k, 5%, 0.25 W, AEC-Q200 Grade 0, 0603", Manufacturer=Rohm, Power_W=250mW, TempCo="200 ppm/C", Tolerance_%=5%, Value2=0.25W, Value_Code=1k00, ValueDisplayed=1.0k
R109 R110 R159 R160 R220 R222: library part CMP-0095938-1, "500 µOhms ±1% 6W Chip Resistor 2512 (6432 Metric) Automotive AEC-Q200, Current Sense Metal Element", Digikey Part Number=CSS2H-2512R-L500FCT-ND, Manufacturer=Bourns, Mouser Part Number=652-CSS2H2512RL500F, Operating Temperature Range="-55°C to +170°C", Power_W=6W, TempCo=100ppm/°C, Tolerance_%=1%
R111 R162 R223: library part CMP-0124268-3, "0.25 mOhms ±1% 3W Chip Resistor 2512 (6332 Metric) Automotive AEC-Q200, Current Sense Metal Element", Digikey Part Number=5705-HoLRS2512-0.25mR-1%TR-ND, Manufacturer="Shenzhen Milliohm Electronic", Operating Temperature Range="-50°C to +170°C", Power_W=3W, TempCo=50ppm/°C, Tolerance_%=1%
R112: library part CMP-0022479-4, "RES, 50, 1%, 0.1 W, AEC-Q200 Grade 0, 0603", Manufacturer=Vishay-Dale, Power_W=100mW, Supplier Part Number 1=89M6778, TempCo="100 ppm/C", Tolerance_%=1%, Value2=0.1W, Value_Code=50R0, ValueDisplayed=50
R113: library part CMP-0025874-4, "RES, 0, 5%, 0.1 W, AEC-Q200 Grade 0, 0603", Manufacturer=Panasonic, Power_W=100mW, Supplier Part Number 1=P0.0GCT-ND, TempCo="600 ppm/C", Tolerance_%=5%, Value2=0.1W, Value_Code=0000, ValueDisplayed=100
R114 R115 R145 R264 R268 R271 R272 R275 R276: library part CMP-0025874-4, "RES, 0, 5%, 0.1 W, AEC-Q200 Grade 0, 0603", Manufacturer=Panasonic, Power_W=100mW, Supplier Part Number 1=P0.0GCT-ND, TempCo="600 ppm/C", Tolerance_%=5%, Value2=0.1W, Value_Code=0000, ValueDisplayed=0
R118: library part CMP-0022479-4, "RES, 50, 1%, 0.1 W, AEC-Q200 Grade 0, 0603", Manufacturer=Vishay-Dale, Power_W=100mW, Supplier Part Number 1=89M6778, TempCo="100 ppm/C", Tolerance_%=1%, Value2=0.1W, Value_Code=50R0, ValueDisplayed=0
R119: library part CMP-0023930-3, "RES, 20.8 k, 0.1%, 0.1 W, 0603", Manufacturer="Yageo America", Power_W=100mW, TempCo="25 ppm/C", Tolerance_%=0.1%, Value2=0.1W, Value_Code=20k8, ValueDisplayed=10k
R120 R122 R128 R207: library part CMP-0092407-1, "Res Thick Film 0603 100K Ohm 0.1% 0.2W(1/5W) ±50ppm/°C Pad SMD Automotive T/R", Digikey Part Number=P20200CT-ND, Manufacturer=Panasonic, Mouser Part Number=667-ERJ-PB3B1003V, Operating Temperature Range="-55°C to +155°C", Power_W=200mW, TempCo=50ppm/°C, Tolerance_%=0.1%
R121: library part CMP-0023900-3, "RES, 1.62 k, 0.1%, 0.1 W, 0603", Manufacturer="Yageo America", Power_W=100mW, TempCo="25 ppm/C", Tolerance_%=0.1%, Value2=0.1W, Value_Code=1k62, ValueDisplayed=1.65k
R126: library part CMP-0023248-5, "RES, 6.20 k, 1%, 0.1 W, 0603", Manufacturer=Yageo, Power_W=100mW, Supplier Part Number 1=311-6.20KHRCT-ND, TempCo="100 ppm/C", Tolerance_%=1%, Value2=0.1W, Value_Code=6k20, ValueDisplayed=6.20k
R133 R143 R144 R147 R148: library part CMP-0082533-1, "RES, 4.99 k, 1%, 0.1 W, 0603", Manufacturer=Vishay-Dale, Power_W=100mW, Supplier Part Number 1=541-3985-1-ND, TempCo="100 ppm/C", Tolerance_%=1%, Value2=0.1W, Value_Code=4k99, ValueDisplayed=4.99k
R135: library part CMP-0078581-1, "RES, 1.00 k, 0.1%, 0.1 W, AEC-Q200 Grade 0, 0603", Manufacturer=Panasonic, Power_W=100mW, Supplier Part Number 1=P1.0KDBCT-ND, TempCo="25 ppm/C", Tolerance_%=0.1%, Value2=0.1W, Value_Code=1k00, ValueDisplayed=1.00k
R146 R290 R291 R292: library part CMP-0022684-2, "RES, 10.0 k, 1%, 0.1 W, 0603", Manufacturer=Panasonic, Power_W=100mW, Supplier Part Number 1=P10.0KHCT-ND, TempCo="100 ppm/C", Tolerance_%=1%, Value2=0.1W, Value_Code=10k0, ValueDisplayed=10.0k
R151: library part CMP-0022680-3, "RES, 1.00 k, 1%, 0.1 W, 0603", Manufacturer=Panasonic, Power_W=100mW, Supplier Part Number 1=P1.00KHCT-ND, TempCo="100 ppm/C", Tolerance_%=1%, Value2=0.1W, Value_Code=1k00, ValueDisplayed=1.00k
R156 R297: library part CMP-0023078-5, "RES, 3.16 k, 1%, 0.1 W, 0603", Manufacturer=Yageo, Power_W=100mW, Supplier Part Number 1=311-3.16KHRCT-ND, TempCo="100 ppm/C", Tolerance_%=1%, Value2=0.1W, Value_Code=3k16, ValueDisplayed=3.16k
R172 R235: library part CMP-0023012-4, "RES, 300 k, 1%, 0.1 W, 0603", Manufacturer=Yageo, Power_W=100mW, Supplier Part Number 1=311-300KHRCT-ND, TempCo="100 ppm/C", Tolerance_%=1%, Value2=0.1W, Value_Code=300k
R175 R236: library part CMP-0023267-5, "RES, 75.0 k, 1%, 0.1 W, 0603", Manufacturer=Yageo, Power_W=100mW, Supplier Part Number 1=311-75.0KHRCT-ND, TempCo="100 ppm/C", Tolerance_%=1%, Value2=0.1W, Value_Code=75k0, ValueDisplayed=75.0k
R188 R249: library part CMP-0022986-5, "RES, 2.20 k, 1%, 0.1 W, 0603", Manufacturer=Yageo, Power_W=100mW, Supplier Part Number 1=311-2.20KHRCT-ND, TempCo="100 ppm/C", Tolerance_%=1%, Value2=0.1W, Value_Code=2k20, ValueDisplayed=2.20k
R189 R250: library part CMP-0022776-5, "RES, 12.1 k, 1%, 0.1 W, 0603", Manufacturer=Yageo, Power_W=100mW, Supplier Part Number 1=311-12.1KHRCT-ND, TempCo="100 ppm/C", Tolerance_%=1%, Value2=0.1W, Value_Code=12k1, ValueDisplayed=12.1k
R192: library part CMP-0096129-1, "50 Ohms ±1% 3.5W Chip Resistor 2512 (6432 Metric) Thick Film", Digikey Part Number=273-ALN2512F50R0E-1TR-ND, Manufacturer=Ohmite, Mouser Part Number=588-ALN2512F50R0E-1, Operating Temperature Range="-55°C to +155°C", Power_W=3.5W, TempCo=150ppm/°C, Tolerance_%=1%
R194: library part CMP-0023013-5, "RES, 300, 1%, 0.1 W, 0603", Manufacturer=Yageo, Power_W=100mW, Supplier Part Number 1=311-300HRCT-ND, TempCo="100 ppm/C", Tolerance_%=1%, Value2=0.1W, Value_Code=300R, ValueDisplayed=300
R195: library part CMP-0042666-1, "Res Metal Strip 2512 0.001 Ohm 1% 3W ±50ppm/C Pad SMD Automotive T/R", Manufacturer="TT Electronics", Mouser Part Number=66-ULRG3R001FLFSLT, Operating Temperature Range=to, Power_W=3W, TempCo=50ppm/°C, Tolerance_%=1%
R198: library part CMP-0022736-4, "RES, 100, 1%, 0.1 W, 0603", Manufacturer=Yageo, Power_W=100mW, Supplier Part Number 1=311-100HRCT-ND, TempCo="100 ppm/C", Tolerance_%=1%, Value2=0.1W, Value_Code=100R, ValueDisplayed=100
R200: library part CMP-0023096-4, "RES, 402 k, 1%, 0.1 W, 0603", Manufacturer=Yageo, Power_W=100mW, Supplier Part Number 1=311-402KHRCT-ND, TempCo="100 ppm/C", Tolerance_%=1%, Value2=0.1W, Value_Code=402k
R201: library part CMP-0022479-2, "RES, 50, 1%, 0.1 W, 0603", Manufacturer=Vishay-Dale, Power_W=100mW, Supplier Part Number 1=89M6778, TempCo="100 ppm/C", Tolerance_%=1%, Value2=0.1W, Value_Code=50R0, ValueDisplayed=100
R203: library part CMP-0023291-5, "RES, 82.5 k, 1%, 0.1 W, 0603", Manufacturer=Yageo, Power_W=100mW, Supplier Part Number 1=311-82.5KHRCT-ND, TempCo="100 ppm/C", Tolerance_%=1%, Value2=0.1W, Value_Code=82k5, ValueDisplayed=82.5k
R211: library part CMP-0022803-5, "RES, 14.7 k, 1%, 0.1 W, 0603", Manufacturer=Yageo, Power_W=100mW, Supplier Part Number 1=311-14.7KHRCT-ND, TempCo="100 ppm/C", Tolerance_%=1%, Value2=0.1W, Value_Code=14k7, ValueDisplayed=14.7k
R212: library part CMP-0023132-5, "RES, 47.5 k, 1%, 0.1 W, 0603", Manufacturer=Yageo, Power_W=100mW, Supplier Part Number 1=311-47.5KHRCT-ND, TempCo="100 ppm/C", Tolerance_%=1%, Value2=0.1W, Value_Code=47k5, ValueDisplayed=47.5k
R213: library part CMP-0022875-5, "RES, 1.33 k, 1%, 0.1 W, 0603", Manufacturer=Yageo, Power_W=100mW, Supplier Part Number 1=311-1.33KHRCT-ND, TempCo="100 ppm/C", Tolerance_%=1%, Value2=0.1W, Value_Code=1k33, ValueDisplayed=1.33k
R263 R269 R274: library part CMP-0078498-1, "RES, 3.00, 1%, 0.1 W, AEC-Q200 Grade 0, 0603", Manufacturer=Rohm, Power_W=100mW, Supplier Part Number 1=RHM3AYCT-ND, TempCo="100 ppm/C", Tolerance_%=1%, Value2=0.1W, Value_Code=3R00, ValueDisplayed=3.00
R278 R279 R280: library part CMP-0022821-5, "RES, 160, 1%, 0.1 W, 0603", Manufacturer=Yageo, Power_W=100mW, Supplier Part Number 1=311-160HRCT-ND, TempCo="100 ppm/C", Tolerance_%=1%, Value2=0.1W, Value_Code=160R, ValueDisplayed=160
R284 R285 R286: library part CMP-0015751-2, "RES, 0.005, 1%, 3 W, AEC-Q200 Grade 0, 2512", Manufacturer=Bourns, Power_W=3W, Supplier Part Number 1=CRE2512-FZ-R005E-3CT-ND, TempCo="75 ppm/C", Tolerance_%=1%, Value_Code=5L000, ValueDisplayed=0.005
R298 R301: library part CMP-0022738-5, "RES, 102, 1%, 0.1 W, 0603", Manufacturer=Yageo, Power_W=100mW, Supplier Part Number 1=311-102HRCT-ND, TempCo="100 ppm/C", Tolerance_%=1%, Value2=0.1W, Value_Code=102R, ValueDisplayed=102
R299: library part CMP-0023037-5, "RES, 33.0 k, 1%, 0.1 W, 0603", Manufacturer=Yageo, Power_W=100mW, Supplier Part Number 1=311-33.0KHRCT-ND, TempCo="100 ppm/C", Tolerance_%=1%, Value2=0.1W, Value_Code=33k0, ValueDisplayed=33.0k
R303: library part CMP-0022814-5, "RES, 15.4 k, 1%, 0.1 W, 0603", Manufacturer=Yageo, Power_W=100mW, Supplier Part Number 1=311-15.4KHRCT-ND, TempCo="100 ppm/C", Tolerance_%=1%, Value2=0.1W, Value_Code=15k4, ValueDisplayed=15.4k
RNTC_1 RNTC_2 RNTC_3: library part CMP-0095715-1, "NTC Thermistor for Temperature Sensor, Automotive, 0603, 47kΩ, 5%, 0.046mA, 5V", B Tolerance=1%, Digikey Part Number=490-NCU18WB473D60RBTR-ND, Manufacturer=Murata, Max Current=0.046mA, Mouser Part Number=81-NCU18WB473D60RB, Operating Temperature Range="-40°C to +150℃", Tolerance_%=5%
S1 S2: library part CMP-0002294-1, "Switch, SPST, Off-On, 50 mA,24V, SMD", CurrentRating_mA=50A, Manufacturer="TE Connectivity", PartNumber=147873-2, Supplier Part Number 1=450-2049-1-ND
SH-J1 SH-J2 SH-J3 SH-J4: library part CMP-0003623-3, "Shunt, 100mil, Gold plated, Black", Alternate Manufacturer=3M, Alternate PartNumber=969102-0000-DA, Manufacturer=Samtec, Supplier Part Number 1=SAM8858-ND
T1 T2 T3 T4 T5 T6 T7 T8 T9: library part CMP-0075010-2, "Terminal 70A Lug", Manufacturer=Panduit, PartNumber=CXS70-14-C, Supplier Part Number 1=CXS70-14-C-ND
TP1 TP2 TP3 TP8 TP9 TP10 TP14 TP15 TP20 TP24 TP25: library part CMP-0055147-2, "Test Point, Multipurpose, Red, TH", Color=Red, Manufacturer="Keystone Electronics", PartNumber=5010, Supplier Part Number 1=36-5010-ND
TP4 TP5 TP6 TP7 TP11 TP12 TP13 TP16 TP17 TP18 TP19 TP21 TP22 TP23 TP26 TP27 TP28 TP39 TP40 TP41 TP42 TP43 TP44 TP45 TP46 TP49 TP50 TP51 TP52 TP53 TP54 TP55 TP56 TP57 TP58: library part CMP-0055149-1, "Test Point, Multipurpose, White, TH", Color=White, Manufacturer=Keystone, PartNumber=5012, Supplier Part Number 1=36-5012-ND
TP29 TP30 TP31 TP32 TP33 TP34 TP35 TP36 TP37 TP38: library part CMP-0055148-2, "Test Point, Multipurpose, Black, TH", Color=Black, Manufacturer="Keystone Electronics", PartNumber=5011, Supplier Part Number 1=36-5011-ND
TP47 TP48: library part CMP-0055139-1, "Test Point, Miniature, White, TH", Color=White, Manufacturer=Keystone, Supplier Part Number 1=36-5002-ND
U1: library part CMP-0095863-1, "Automotive H-Bridge Driver with Integrated Current Sense and Diagnostics", Manufacturer="Texas Instruments", Max Supply Voltage=35V, Min Supply Voltage=4.5V, Nominal Supply Current=10mA, Operating Temperature Range="-40°C to +150°C", Switching Frequency=25kHz
U2: library part CMP-0121932-1, "Automotive 65-V H-Bridge Driver with Integrated Current Sense and Diagnostics", Manufacturer="Texas Instruments", Max Supply Voltage=65V, Min Supply Voltage=3V, Nominal Supply Current=3mA, Operating Temperature Range="-40°C to +150°C", Switching Frequency=0-100kHz
U3: library part CMP-0121394-1, "Low IQ Smart High Side gate driver with I2t, Low Power Mode and Diagnostics", Manufacturer="Texas Instruments", Operating Temperature Range=to
U4: library part CMP-0096221-1, "3.5V to 65V Synchronous Step-Down Voltage Regulator", Manufacturer="Texas Instruments", Operating Temperature Range=to
U5: library part CMP-0093448-1, "3-V to 18-V, High Efficiency and Low IQ Buck Converter in QFN HR  Package with 165C Junction temperature", Manufacturer="Texas Instruments", Max Supply Voltage=18V, Min Supply Voltage=3V, Nominal Supply Current=8mA, Operating Temperature Range="-55°C to +165°C", Output Voltage=0.4-5.5V, Switching Frequency=1/2.5MHz
U6: library part CMP-0124507-1, "5mΩ, Automotive Dual-Channel, SPI Controlled High-Side Switch with Integrated I2 t Wire Protection and low power mode", Manufacturer="Texas Instruments", Max Supply Voltage=18V, Min Supply Voltage=6V, Nominal Supply Current=2-4.9mA, Operating Temperature Range="-40°C to +125°C"
U7: library part CMP-0098417-1, Manufacturer="Texas Instruments", Operating Temperature Range=to
U8: library part CMP-0038451-2, "1A, 120-mΩ Quad-Channel Smart High-Side Switch", Manufacturer="Texas Instruments", Max Supply Voltage=18V, Min Supply Voltage=6V, Nominal Supply Current=1.3-4.9mA, Operating Temperature Range="-40°C to +125°C"
U9: library part CMP-0122616-1, "Automotive ideal diode with circuit breaker, under- and overvoltage protection with fault output 24-VQFN -40 to 125", Digikey Part Number=296-LM74900QRGERQ1CT-ND, Manufacturer="Texas Instruments", Max Supply Voltage=65V, Min Supply Voltage=3V, Mouser Part Number=595-LM74900QRGERQ1, Nominal Supply Current=630-635uA, Operating Temperature Range="-40°C to +125°C"
U10: library part CMP-0122244-1, "48-V, 85-mΩ Dual-Channel Smart High-Side Switch", Manufacturer="Texas Instruments", Max Supply Voltage=64V, Min Supply Voltage=6V, Operating Temperature Range="-40°C to +125°C"
U11: library part CMP-0097835-1, "30-mΩ, 24-V, 6-A Single-Channel Automotive Smart High-Side Switch", Manufacturer="Texas Instruments", Max Supply Voltage=48V, Min Supply Voltage=6V, Nominal Supply Current=0.98-1mA, Operating Temperature Range="-40°C to +125°C"
U12 U15: library part CMP-0124371-1, "Low IQ Automotive High Side Switch Controller with Bi-directional IMON, Low Power Mode, Load Wakeup, I2t and Diagnostics", Manufacturer="Texas Instruments", Max Supply Voltage=73V, Min Supply Voltage=3.5V, Operating Temperature Range="-40°C to +150°C"
U13: library part CMP-0123509-1, Manufacturer="Texas Instruments", Operating Temperature Range=to
U14: library part CMP-0124514-1, "Automotive 3.5-V to 40-V high-side driver with protection and diagnostics 19-VSSOP -40 to 125", Digikey Part Number=296-TPS12111LQDGXRQ1CT-ND, Manufacturer="Texas Instruments", Max Supply Voltage=40V, Min Supply Voltage=3.5V, Mouser Part Number=595-TPS12111LQDGXRQ1, Nominal Supply Current=613uA, Operating Temperature Range="-40°C to +125°C"
U16: library part CMP-0122985-1, "48V Battery Three-Phase Smart Gate Driver with Accurate Current Sensing and Advanced Monitoring", Manufacturer="Texas Instruments", Max Supply Voltage=85V, Min Supply Voltage=8V, Operating Temperature Range="-40°C to +150°C"
U17: library part CMP-0122953-2, Manufacturer="Texas Instruments", Operating Temperature Range=to
ZZ1: library part CMP-0003616-3
ZZ2: library part CMP-0077236-1
ZZ3: library part CMP-0077237-1
ZZ4: library part CMP-0077238-1

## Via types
v1: diameter 0.635, hole 0.254, Top Shielding/Sig to Bottom Shielding/Sig, tented both sides, 778 vias
v2: diameter 0.6, hole 0.254, Top Shielding/Sig to Bottom Shielding/Sig, tented both sides, 726 vias
v3: diameter 0.813, hole 0.406, Top Shielding/Sig to Bottom Shielding/Sig, 522 vias
v4: diameter 0.5, hole 0.2, Top Shielding/Sig to Bottom Shielding/Sig, tented both sides, 95 vias
v5: diameter 0.5, hole 0.2, Top Shielding/Sig to Bottom Shielding/Sig, 39 vias
v6: diameter 0.635, hole 0.254, Top Shielding/Sig to Bottom Shielding/Sig, 10 vias
v7: diameter 0.63, hole 0.33, Top Shielding/Sig to Bottom Shielding/Sig, tented both sides, 6 vias
v8: diameter 0.75, hole 0.254, Top Shielding/Sig to Bottom Shielding/Sig, tented both sides, 6 vias
v9: diameter 0.5, hole 0.2, Top Shielding/Sig to Bottom Shielding/Sig, tented top, 3 vias

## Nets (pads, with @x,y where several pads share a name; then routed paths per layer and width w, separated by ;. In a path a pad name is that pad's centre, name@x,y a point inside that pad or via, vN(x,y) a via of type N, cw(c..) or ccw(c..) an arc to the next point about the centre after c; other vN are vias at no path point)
1HTC30_DIAG_EN_5: J4.2 U11.3 | length 22.2
  Top Shielding/Sig w0.25: U11.3@21.9,24.05 21.9,26.296 22,26.396 v1(22,26.5)
  Sig 1 w0.25: J4.2@7.75,22.75 7.75,22.5 9.25,21 11.25,21 11.5,21.25 11.5,23.75 15.25,27.5 19.5,27.5 20.5,26.5 v1(22,26.5)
